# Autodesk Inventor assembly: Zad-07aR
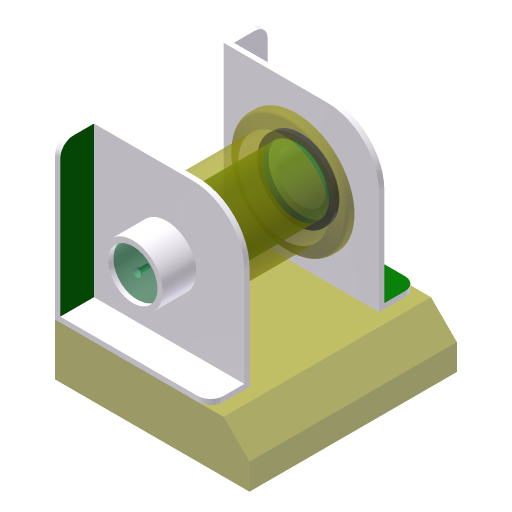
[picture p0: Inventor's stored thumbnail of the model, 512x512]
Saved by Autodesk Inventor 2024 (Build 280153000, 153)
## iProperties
Company: ATC
Created: 2023-03
Part Number: Zad-07aR
Document SubType Name: Assembly
Designer: Andrzej Jaskulski
Checked By: A.J.
Engr Approved By: Andrzej Jaskulski
Mfg Approved By: Andrzej Jaskulski
Authority: A.J.
Author: Andrzej Jaskulski
Title: A.J.: Kurs R2024-MEP
Revision Number: 1/24
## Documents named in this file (4)
- C:\Users\AndJas\Documents\R2024-MEP\Obszar roboczy\Zad-07aR.iam
- C:\Users\AndJas\Documents\R2024-MEP\Obszar roboczy\PŁYTA.ipt
- C:\Users\AndJas\Documents\R2024-MEP\Obszar roboczy\WSP.ipt
- C:\Users\AndJas\Documents\R2024-MEP\Obszar roboczy\PZESP1.iam
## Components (4 placed, 3 different names)
1. PŁYTA:1 — Sztywne:1, Sztywne:2
2. WSP:1 — Obrotowe:1, Sztywne:1
3. WSP:2 — Sztywne:2
4. PZESP1:1 [sub-assembly] — Obrotowe:1
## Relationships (3: WeldJoint 2, RevoluteJoint 1)
- Sztywne:1 [WeldJoint]: PŁYTA:1 ↔ WSP:1
- Sztywne:2 [WeldJoint]: PŁYTA:1 ↔ WSP:2
- Obrotowe:1 [RevoluteJoint]: WSP:1 ↔ PZESP1:1
